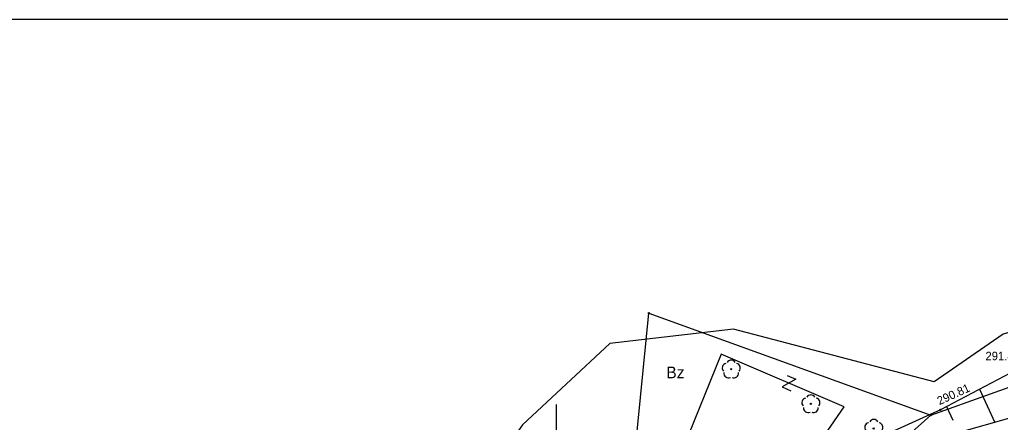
# Model space of a CAD drawing. Extents: x 7477803 to 7478145, y 5500698 to 5500984.
# Drawn here: x 7477856.6 to 7477935.9, y 5500951.1 to 5500983.6 of the extents above; entities that cross this region are included whole.
import ezdxf

# ---------------------------------------------------------------- set-up
doc = ezdxf.new("R2010")
doc.units = 0
for name, color, linetype in [('203-Punkt załamania granicy działki nie stabilizowany', 7, 'Continuous'), ('gr_dzialki', 7, 'Continuous'), ('gr_klasy', 7, 'Continuous'), ('gr_uzytek', 7, 'Continuous'), ('ogr_symb', 7, 'Continuous'), ('opis_uzytek', 7, 'Continuous'), ('pkt_wys', 7, 'Continuous'), ('przehaczenie', 7, 'Continuous'), ('robocza11', 7, 'Continuous'), ('robocza49', 7, 'Continuous'), ('rzeka', 7, 'Continuous'), ('skarp_wypel', 7, 'Continuous'), ('skarpa_gora', 7, 'Continuous'), ('zakresy', 7, 'Continuous'), ('zielen', 7, 'Continuous')]:
    doc.layers.add(name, color=color, linetype=linetype)

# ---------------------------------------------------------------- blocks, each defined once
blk = doc.blocks.new('203')
blk.add_circle((0, 0), 0.045)
blk = doc.blocks.new('922_5')
at = {"layer": 'zielen'}
blk.add_circle((-0.001, 0), 0.05, dxfattribs=at)
blk.add_circle((-0.001, 0), 0.05, dxfattribs=at)
for centre, start, end in [((-0.353, 0.098), 101.99877, 221.97586), ((0.004, 0.357), 30.12432, 149.87568), ((0.361, 0.098), 318.02414, 78.00123), ((-0.215, -0.321), 174.33504, 293.76069), ((0.224, -0.321), 246.23931, 5.66496)]:
    blk.add_arc(centre, 0.375, start, end, dxfattribs=at)
blk = doc.blocks.new('801_5')
at = {"layer": 'pkt_wys'}
blk.add_circle((0, 0), 0.05, dxfattribs=at)
blk.add_circle((0, 0), 0.05, dxfattribs=at)
blk = doc.blocks.new('991_5_1')
at = {"layer": 'przehaczenie'}
blk.add_lwpolyline([(-0.38, 0.5), (0.38, 0.5), (-0.38, -0.5), (0.38, -0.5)], dxfattribs=at)

msp = doc.modelspace()

# ---------------------------------------------------------------- linework, layer by layer
at = {"layer": 'gr_dzialki'}
for points in [[(7477905.2, 5500937.01), (7477907.46, 5500959.88)], [(7477907.46, 5500959.88), (7477930.25, 5500951.63)], [(7477914.79, 5500937.8), (7477930.25, 5500951.63)]]:
    msp.add_lwpolyline(points, dxfattribs=at)
at = {"layer": 'gr_klasy'}
for points in [[(7477905.2, 5500937.01), (7477907.46, 5500959.88)], [(7477907.46, 5500959.88), (7477930.25, 5500951.63)], [(7477930.25, 5500951.63), (7477939.89, 5500955.07)]]:
    msp.add_lwpolyline(points, dxfattribs=at)
at = {"layer": 'gr_uzytek'}
msp.add_lwpolyline([(7477930.25, 5500951.63), (7477914.79, 5500937.8), (7477911.91, 5500931.81)], dxfattribs=at)
at = {"layer": 'ogr_symb'}
msp.add_lwpolyline([(7477905.522, 5500937.143), (7477911.344, 5500935.069), (7477923.26, 5500952.316), (7477913.315, 5500956.56), (7477910.221, 5500948.909), (7477909.82, 5500947.989), (7477905.522, 5500937.143)], dxfattribs=at)
at = {"layer": 'robocza11'}
msp.add_lwpolyline([(7478014.996, 5500697.565), (7478144.729, 5500697.565), (7478144.729, 5500983.565), (7477803.256, 5500983.565), (7477803.256, 5500697.565), (7478010.821, 5500697.565)], close=True, dxfattribs=at)
at = {"layer": 'robocza49'}
msp.add_line((7477900, 5500947.5), (7477900, 5500952.5), dxfattribs=at)
at = {"layer": 'rzeka'}
msp.add_lwpolyline([(7477958.237, 5500959.69), (7477946.953, 5500954.328), (7477932.158, 5500950.132), (7477925.095, 5500947.293), (7477916.965, 5500936.975), (7477910.703, 5500929.638)], dxfattribs=at)
at = {"layer": 'skarp_wypel'}
for p, q in [((7477934.172, 5500953.726), (7477935.421, 5500951.057)), ((7477931.514, 5500952.328), (7477932.025, 5500951.235))]:
    msp.add_line(p, q, dxfattribs=at)
at = {"layer": 'skarpa_gora'}
msp.add_lwpolyline([(7477954.915, 5500961.267), (7477949.527, 5500959.741), (7477937.672, 5500955.568), (7477931.026, 5500952.071), (7477922.66, 5500948.261), (7477921.203, 5500945.67), (7477915.569, 5500939.354), (7477913.682, 5500934.983), (7477911.207, 5500932.609), (7477909.481, 5500929.955)], dxfattribs=at)
at = {"layer": 'zakresy'}
msp.add_lwpolyline([(7477995.059, 5500962.348), (7477983.951, 5500968.084), (7477970.781, 5500968.613), (7477936.09, 5500958.171), (7477930.511, 5500954.336), (7477914.305, 5500958.58), (7477904.32, 5500957.41), (7477897.265, 5500950.868), (7477811.424, 5500829.338), (7477936.003, 5500769.492), (7478008.982, 5500726.585), (7478019.402, 5500721.781), (7478037.95, 5500734.97), (7478039.493, 5500755.094), (7478043.98, 5500765.708), (7478067.545, 5500795.068), (7478092.109, 5500820.25), (7478076.156, 5500837.989), (7478068.105, 5500851.146), (7478061.422, 5500873.298), (7478054.135, 5500876.371), (7478039.669, 5500897.644), (7478026.36, 5500915.23), (7478015.054, 5500927.728)], close=True, dxfattribs=at)

# ---------------------------------------------------------------- block references
at = {"layer": '203-Punkt załamania granicy działki nie stabilizowany'}
for p in [(7477907.46, 5500959.88), (7477930.25, 5500951.63)]:
    msp.add_blockref('203', p, dxfattribs=at)
at = {"layer": 'pkt_wys', "rotation": 0.0626175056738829}
msp.add_blockref('801_5', (7477931.026, 5500952.071), dxfattribs=at)
at = {"layer": 'przehaczenie', "rotation": -23.110134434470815}
msp.add_blockref('991_5_1', (7477918.788, 5500954.224), dxfattribs=at)
at = {"layer": 'zielen', "rotation": 0.0626175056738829}
for p in [(7477914.121, 5500955.353), (7477920.559, 5500952.543), (7477925.64, 5500950.565)]:
    msp.add_blockref('922_5', p, dxfattribs=at)

# ---------------------------------------------------------------- texts
at = {"layer": 'opis_uzytek'}
msp.add_text('Bz', height=0.94, dxfattribs=at).set_placement((7477908.88, 5500954.62))
at = {"layer": 'pkt_wys'}
for s, rotation, p in [('291.42', 0.06262, (7477934.666, 5500956.074)), ('290.81', 24.33706, (7477930.947, 5500952.44))]:
    msp.add_text(s, height=0.68, rotation=rotation, dxfattribs=at).set_placement(p)

doc.saveas('drawing.dxf')
